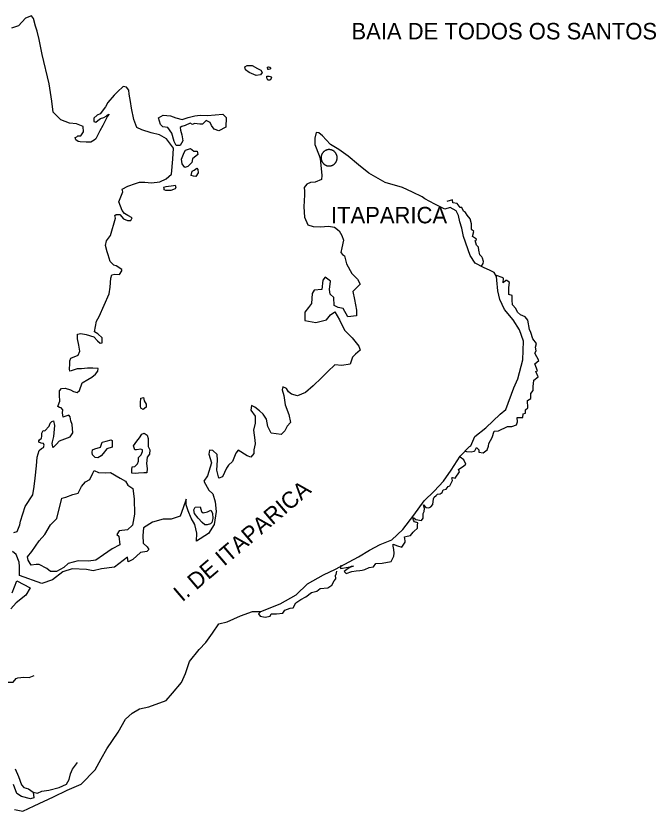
# Model space of a CAD drawing. Extents: x 662444 to 1640468, y 7452018 to 9606170.
# Drawn here: x 1173727 to 1199796, y 8540001 to 8572398 of the extents above; entities that cross this region are included whole.
import ezdxf

# ---------------------------------------------------------------- set-up
doc = ezdxf.new("R2010")
doc.units = 0
doc.layers.add('Level 1', color=7, linetype='Continuous')
doc.layers.add('Level 3', color=7, linetype='Continuous')

msp = doc.modelspace()

# ---------------------------------------------------------------- linework, layer by layer
at = {"layer": 'Level 1'}
for points in [[(1178235, 8569500), (1178093, 8569515), (1177870, 8569309), (1177725, 8569168), (1177466, 8568874), (1177375, 8568698), (1177160, 8568403), (1177039, 8568350), (1176905, 8568231), (1176902, 8568098), (1176977, 8568062), (1177066, 8568138), (1177177, 8568213), (1177309, 8568255), (1177398, 8568319), (1177454, 8568373), (1177520, 8568394), (1177453, 8568318), (1177269, 8567933), (1177143, 8567713), (1177029, 8567494), (1176983, 8567384), (1176916, 8567330), (1176783, 8567255), (1176586, 8567249), (1176347, 8567266), (1176260, 8567279), (1176163, 8567348), (1176144, 8567437), (1176210, 8567469), (1176244, 8567513), (1176374, 8567510), (1176477, 8567674), (1176460, 8567897), (1176190, 8568004), (1175907, 8568033), (1175561, 8568164), (1175241, 8568472), (1175187, 8568929), (1175084, 8569632), (1174796, 8570830), (1174669, 8571433), (1174589, 8571769), (1174518, 8571982), (1174449, 8572295), (1174365, 8572398), (1174111, 8572303), (1173831, 8571999), (1173545, 8571894)], [(1183227, 8570090), (1183077, 8570194), (1183047, 8570328), (1183147, 8570382), (1183354, 8570376), (1183570, 8570260), (1183699, 8570190), (1183751, 8570089), (1183683, 8569990), (1183508, 8569972), (1183227, 8570090)], [(1184071, 8570225), (1184016, 8570216), (1183983, 8570216), (1183975, 8570306), (1184008, 8570316), (1184073, 8570314), (1184105, 8570280), (1184071, 8570225)], [(1184082, 8569780), (1183984, 8569782), (1183952, 8569839), (1183943, 8569906), (1183944, 8569939), (1184042, 8569937), (1184096, 8569935), (1184138, 8569868), (1184082, 8569780)], [(1175879, 8556130), (1175724, 8556078), (1175647, 8556047), (1175619, 8556225), (1175633, 8556347), (1175569, 8556427), (1175504, 8556440), (1175440, 8556486), (1175487, 8556640), (1175510, 8556695), (1175495, 8556940), (1175499, 8557129), (1175578, 8557217), (1175731, 8557235), (1175947, 8557163), (1176077, 8557093), (1176218, 8557056), (1176318, 8557143), (1176424, 8557452), (1176656, 8557580), (1176822, 8557676), (1176967, 8557806), (1177057, 8557926), (1177082, 8558036), (1176853, 8558042), (1176646, 8558047), (1176394, 8558020), (1176219, 8558013), (1175977, 8557941), (1175922, 8557920), (1175903, 8558010), (1175919, 8558221), (1175922, 8558343), (1175957, 8558453), (1176266, 8558579), (1176335, 8558733), (1176286, 8558979), (1176238, 8559247), (1176232, 8559425), (1176375, 8559455), (1176592, 8559417), (1176895, 8559320), (1177044, 8559161), (1177161, 8559058), (1177238, 8559078), (1177243, 8559278), (1177061, 8559439), (1176933, 8559531), (1177009, 8559963), (1177123, 8560149), (1177527, 8561074), (1177567, 8561351), (1177597, 8561706), (1177633, 8561850), (1177754, 8561880), (1177939, 8561865), (1178041, 8562007), (1178042, 8562062), (1177806, 8562213), (1177709, 8562248), (1177559, 8562386), (1177490, 8562665), (1177449, 8562789), (1177379, 8563046), (1177416, 8563235), (1177585, 8563453), (1177777, 8564160), (1177758, 8564272), (1177813, 8564304), (1177955, 8564301), (1178104, 8564130), (1178266, 8564059), (1178408, 8564056), (1178465, 8564177), (1178282, 8564270), (1178153, 8564351), (1178057, 8564465), (1177913, 8564824), (1178087, 8565232), (1178057, 8565333), (1178278, 8565461), (1178597, 8565564), (1178762, 8565627), (1178981, 8565622), (1179253, 8565593), (1179581, 8565640), (1179846, 8565756), (1180058, 8565951), (1180117, 8566562), (1180139, 8567006), (1179853, 8567391), (1179574, 8567554), (1179237, 8567629), (1178858, 8567761), (1178653, 8567855), (1178530, 8568180), (1178432, 8568639), (1178395, 8568907), (1178337, 8569209), (1178319, 8569376), (1178235, 8569500)], [(1180495, 8568177), (1180737, 8568260), (1181012, 8568331), (1181230, 8568348), (1181525, 8568341), (1181842, 8568366), (1182148, 8568392), (1182287, 8568255), (1182277, 8567866), (1181990, 8567717), (1181795, 8567778), (1181690, 8567936), (1181638, 8568049), (1181476, 8568131), (1181320, 8567990), (1181222, 8567992), (1180993, 8568009), (1180916, 8567977), (1180829, 8568024), (1180620, 8567929), (1180488, 8567888), (1180421, 8567845), (1180430, 8567745), (1180480, 8567554), (1180528, 8567308), (1180414, 8567122), (1180250, 8567115), (1180167, 8567284), (1180077, 8567620), (1179919, 8567846), (1179713, 8567884), (1179617, 8567976), (1179536, 8568245), (1179724, 8568351), (1180018, 8568333), (1180234, 8568239), (1180495, 8568177)], [(1176381, 8541099), (1176951, 8541686), (1177192, 8542136), (1177431, 8542542), (1177895, 8543220), (1178191, 8543747), (1178459, 8543985), (1178758, 8544166), (1179141, 8544246), (1179846, 8544507), (1180104, 8544812), (1180464, 8545237), (1180626, 8545611), (1180791, 8546096), (1181195, 8546587), (1181464, 8546870), (1181736, 8547252), (1181985, 8547635), (1182336, 8547705), (1182877, 8547958), (1183361, 8548135), (1183699, 8548127), (1184492, 8548441), (1185145, 8548814), (1185603, 8549259), (1186246, 8549632), (1186742, 8549853), (1187682, 8550364), (1188125, 8550631), (1188557, 8550865), (1189041, 8551053), (1189477, 8551476), (1189928, 8552055), (1190358, 8552645), (1190760, 8553035), (1191142, 8553449), (1191447, 8553886), (1191822, 8554455), (1192203, 8554857), (1192247, 8554879), (1192420, 8555264), (1192866, 8555609), (1193447, 8556173), (1193681, 8556367), (1194009, 8557249), (1194160, 8557612), (1194376, 8558386), (1194395, 8559142), (1194232, 8559614), (1193970, 8560021), (1193620, 8560430), (1193434, 8560847), (1193355, 8561194), (1193311, 8561629), (1193293, 8561774), (1193199, 8561943), (1193037, 8562025), (1192767, 8562143), (1192433, 8562318), (1192223, 8562635), (1191959, 8563410), (1191880, 8563745), (1191799, 8564003), (1191751, 8564272), (1191657, 8564452), (1191409, 8564592), (1191190, 8564530), (1190780, 8564730), (1190381, 8564940), (1190274, 8565032), (1189875, 8565220), (1189465, 8565408), (1188760, 8565615), (1188093, 8565987), (1187676, 8566331), (1187259, 8566687), (1186872, 8566952), (1186539, 8567160), (1186358, 8567354), (1186209, 8567514), (1186060, 8567640), (1185951, 8567653), (1185901, 8567421), (1185895, 8567154), (1186080, 8566716), (1186110, 8566593), (1186180, 8565890), (1186176, 8565734), (1185911, 8565618), (1185726, 8565612), (1185571, 8565538), (1185470, 8565407), (1185477, 8565251), (1185473, 8565106), (1185450, 8564617), (1185483, 8564194), (1185618, 8563890), (1185834, 8563818), (1186129, 8563810), (1186457, 8563836), (1186696, 8563785)], [(1180582, 8566829), (1180628, 8566928), (1180837, 8566989), (1180976, 8566886), (1181107, 8566882), (1181137, 8566748), (1180914, 8566576), (1180888, 8566420), (1180721, 8566258), (1180600, 8566227), (1180494, 8566375), (1180466, 8566564), (1180582, 8566829)], [(1186809, 8566609), (1186809, 8566620), (1186809, 8566632), (1186808, 8566643), (1186807, 8566655), (1186805, 8566667), (1186803, 8566678), (1186801, 8566690), (1186798, 8566701), (1186795, 8566712), (1186792, 8566724), (1186788, 8566734), (1186784, 8566745), (1186780, 8566756), (1186775, 8566766), (1186770, 8566777), (1186763, 8566787), (1186758, 8566797), (1186752, 8566806), (1186744, 8566816), (1186738, 8566825), (1186731, 8566834), (1186723, 8566842), (1186715, 8566851), (1186707, 8566859), (1186699, 8566867), (1186690, 8566874), (1186681, 8566882), (1186672, 8566889), (1186662, 8566895), (1186653, 8566902), (1186643, 8566908), (1186633, 8566913), (1186623, 8566918), (1186612, 8566923), (1186602, 8566928), (1186591, 8566931), (1186580, 8566935), (1186570, 8566938), (1186558, 8566941), (1186547, 8566943), (1186536, 8566946), (1186524, 8566947), (1186513, 8566949), (1186501, 8566950), (1186490, 8566950), (1186479, 8566951), (1186467, 8566950), (1186456, 8566949), (1186444, 8566948), (1186433, 8566946), (1186422, 8566944), (1186410, 8566942), (1186399, 8566939), (1186388, 8566936), (1186377, 8566933), (1186367, 8566929), (1186356, 8566925), (1186345, 8566920), (1186335, 8566915), (1186325, 8566910), (1186315, 8566903), (1186305, 8566898), (1186297, 8566892), (1186287, 8566884), (1186278, 8566878), (1186269, 8566870), (1186261, 8566862), (1186252, 8566854), (1186244, 8566846), (1186236, 8566838), (1186230, 8566829), (1186222, 8566819), (1186215, 8566810), (1186209, 8566800), (1186202, 8566791), (1186197, 8566781), (1186191, 8566771), (1186186, 8566760), (1186182, 8566749), (1186177, 8566739), (1186174, 8566728), (1186170, 8566717), (1186166, 8566706), (1186164, 8566694), (1186161, 8566682), (1186159, 8566671), (1186158, 8566659), (1186156, 8566648), (1186155, 8566636), (1186155, 8566625), (1186154, 8566614), (1186155, 8566601), (1186156, 8566590), (1186157, 8566578), (1186159, 8566567), (1186161, 8566556), (1186162, 8566543), (1186165, 8566532), (1186168, 8566521), (1186171, 8566510)], [(1186171, 8566510), (1186176, 8566500), (1186180, 8566488), (1186184, 8566477), (1186189, 8566467), (1186194, 8566457), (1186200, 8566447), (1186206, 8566437), (1186212, 8566428), (1186219, 8566417), (1186226, 8566408), (1186233, 8566399), (1186241, 8566391), (1186249, 8566382), (1186256, 8566374), (1186265, 8566366), (1186274, 8566359), (1186283, 8566351), (1186292, 8566344), (1186301, 8566339), (1186311, 8566332), (1186321, 8566326), (1186330, 8566320), (1186341, 8566315), (1186352, 8566311), (1186362, 8566306), (1186373, 8566302), (1186383, 8566299), (1186394, 8566295), (1186406, 8566293), (1186417, 8566290), (1186428, 8566288), (1186440, 8566286), (1186451, 8566285), (1186463, 8566283), (1186474, 8566283), (1186485, 8566283), (1186497, 8566284), (1186508, 8566284), (1186520, 8566285), (1186531, 8566287), (1186541, 8566289), (1186554, 8566291), (1186565, 8566294), (1186576, 8566297), (1186587, 8566300), (1186596, 8566305), (1186607, 8566309), (1186618, 8566313), (1186628, 8566318), (1186638, 8566324), (1186648, 8566330), (1186658, 8566335), (1186667, 8566342), (1186677, 8566349), (1186686, 8566356), (1186695, 8566363), (1186703, 8566371), (1186712, 8566380), (1186720, 8566387), (1186728, 8566396), (1186734, 8566405), (1186742, 8566414), (1186749, 8566423), (1186755, 8566433), (1186761, 8566443), (1186767, 8566453), (1186773, 8566463), (1186777, 8566474), (1186782, 8566485), (1186787, 8566495), (1186790, 8566506), (1186794, 8566517), (1186797, 8566528), (1186800, 8566540), (1186802, 8566551), (1186805, 8566562), (1186806, 8566574), (1186808, 8566585), (1186809, 8566597), (1186809, 8566609)], [(1181049, 8565860), (1180962, 8565862), (1180865, 8565898), (1180902, 8566075), (1180990, 8566106), (1181101, 8566193), (1181132, 8566136), (1181151, 8566002), (1181049, 8565860)], [(1180145, 8565493), (1180211, 8565503), (1180242, 8565413), (1180218, 8565347), (1180031, 8565284), (1179834, 8565278), (1179770, 8565313), (1179760, 8565369), (1179751, 8565425), (1179849, 8565445), (1180145, 8565493)], [(1192692, 8562201), (1192761, 8562310), (1192774, 8562388), (1192722, 8562523), (1192702, 8562579), (1192617, 8562670), (1192578, 8562849), (1192559, 8562972), (1192485, 8563063), (1192435, 8563253), (1192456, 8563230), (1192480, 8563297), (1192319, 8563412), (1192378, 8563611), (1192282, 8563691), (1192284, 8563769), (1192277, 8563925), (1192227, 8564126), (1192100, 8564274), (1192037, 8564387), (1191952, 8564445), (1191890, 8564591), (1191824, 8564593), (1191697, 8564752), (1191523, 8564778), (1191504, 8564901), (1191274, 8564840)], [(1186696, 8563785), (1186889, 8563647), (1187004, 8563455), (1187065, 8563264), (1187002, 8562943), (1186965, 8562755), (1187028, 8562675), (1187114, 8562618), (1187194, 8562293), (1187413, 8561909), (1187637, 8561670), (1187741, 8561467), (1187449, 8561163), (1187518, 8560850), (1187594, 8560403), (1187600, 8560180), (1187238, 8560144), (1187050, 8560483), (1186855, 8560521), (1186682, 8560603), (1186679, 8560926), (1186530, 8561063), (1186502, 8561253), (1186532, 8561597), (1186318, 8561747), (1186228, 8561638), (1186185, 8561250), (1185868, 8561224), (1185789, 8561093), (1185757, 8560682), (1185643, 8560518), (1185486, 8560333), (1185499, 8559987), (1185934, 8559910), (1186373, 8560010), (1186531, 8560218), (1186708, 8560336), (1186908, 8560019), (1187105, 8559591), (1187414, 8559283), (1187689, 8558943), (1187739, 8558786), (1187561, 8558612), (1187427, 8558493), (1187332, 8558206), (1186993, 8558159), (1186709, 8558177), (1186430, 8557917), (1186173, 8557656), (1185826, 8557331), (1185525, 8557060), (1185194, 8556913), (1184956, 8556986), (1184827, 8557078), (1184743, 8557224), (1184592, 8557284), (1184567, 8557162), (1184638, 8556927), (1184694, 8556547), (1184837, 8556154), (1184905, 8555830), (1184771, 8555688), (1184678, 8555490), (1184533, 8555349), (1184120, 8555393), (1183984, 8555663), (1183926, 8555965), (1183790, 8556169), (1183651, 8556306), (1183459, 8556455), (1183318, 8556525), (1183292, 8556337), (1183471, 8556088), (1183475, 8555809), (1183403, 8555522), (1183458, 8555109), (1183476, 8554964), (1183416, 8554721), (1183412, 8554576), (1183288, 8554423), (1183147, 8554471), (1182771, 8554703), (1182681, 8554583), (1182542, 8554242), (1182385, 8554101), (1182306, 8553969), (1182133, 8553617), (1181990, 8553565), (1181911, 8553890), (1181932, 8554301), (1181927, 8554524), (1181746, 8554695), (1181604, 8554710), (1181589, 8554543), (1181689, 8554185), (1181523, 8553655), (1181376, 8553436), (1181585, 8553075), (1181745, 8552926), (1181846, 8552601), (1181880, 8552200)], [(1191991, 8554674), (1192078, 8554649), (1192263, 8554644), (1192384, 8554664), (1192417, 8554685), (1192486, 8554817), (1192581, 8554714), (1192580, 8554681), (1192579, 8554625), (1192753, 8554599), (1192920, 8554717), (1192978, 8554871), (1192981, 8554982), (1193118, 8555224), (1193201, 8555478), (1193376, 8555496), (1193740, 8555664), (1193926, 8555671), (1194113, 8555733), (1194149, 8555866), (1194142, 8556033), (1194284, 8556040), (1194372, 8556038), (1194386, 8556182), (1194474, 8556214), (1194478, 8556347), (1194578, 8556434), (1194563, 8556723), (1194697, 8556809), (1194691, 8557020), (1194792, 8557140), (1194786, 8557319), (1194799, 8557407), (1194824, 8557551), (1194992, 8557692), (1194899, 8557906), (1194965, 8557937), (1194852, 8558218), (1195019, 8558359), (1194852, 8558652), (1194909, 8558751), (1194891, 8558896), (1194928, 8559051), (1194780, 8559244), (1194699, 8559502), (1194636, 8559626), (1194569, 8559995), (1194463, 8560131), (1194269, 8560225), (1194152, 8560328), (1194079, 8560474), (1193952, 8560633), (1193935, 8560823), (1193940, 8561012), (1193799, 8561049), (1193803, 8561205), (1193806, 8561327), (1193833, 8561538), (1193715, 8561619), (1193682, 8561620), (1193571, 8561522), (1193586, 8561711), (1193522, 8561746), (1193294, 8561818)], [(1179032, 8556576), (1179029, 8556464), (1178906, 8556356), (1178809, 8556414), (1178801, 8556503), (1178804, 8556637), (1178809, 8556826), (1178918, 8556845), (1178948, 8556722), (1179032, 8556576)], [(1173645, 8551346), (1173777, 8551387), (1173893, 8551662), (1173918, 8551817), (1174107, 8552413), (1174414, 8552884), (1174466, 8553228), (1174517, 8553560), (1174563, 8554071), (1174593, 8554415), (1174676, 8554691), (1174765, 8554767), (1174854, 8554820), (1174878, 8554909), (1174847, 8554976), (1174760, 8554989), (1174663, 8555036), (1174664, 8555092), (1174687, 8555125), (1174765, 8555190), (1174778, 8555278), (1174781, 8555401), (1174838, 8555510), (1174903, 8555498), (1175082, 8555682), (1175118, 8555804), (1175196, 8555880), (1175251, 8555901), (1175301, 8555710), (1175257, 8555266), (1175197, 8555045), (1175185, 8554979), (1175214, 8554845), (1175246, 8554811), (1175369, 8554941), (1175504, 8555082), (1175724, 8555166), (1175933, 8555250), (1176046, 8555414), (1176011, 8555749), (1175960, 8555894), (1175931, 8556062), (1175879, 8556130)], [(1178758, 8555214), (1178860, 8555356), (1178948, 8555398), (1179066, 8555318), (1179106, 8555183), (1179114, 8555038), (1179109, 8554849), (1179182, 8554714), (1179167, 8554536), (1179077, 8554416), (1179049, 8554161), (1179065, 8553960), (1179061, 8553782), (1178941, 8553785), (1178722, 8553768), (1178591, 8553761), (1178450, 8553764), (1178453, 8553909), (1178456, 8554020), (1178565, 8554039), (1178677, 8554148), (1178713, 8554258), (1178716, 8554403), (1178828, 8554511), (1178886, 8554654), (1178888, 8554721), (1178812, 8554745), (1178637, 8554716), (1178571, 8554718), (1178521, 8554886), (1178645, 8555072), (1178758, 8555214)], [(1177167, 8554830), (1177237, 8555029), (1177402, 8555069), (1177599, 8555120), (1177653, 8555096), (1177647, 8554830), (1177427, 8554757), (1177280, 8554572), (1177202, 8554473), (1177058, 8554388), (1176949, 8554413), (1176843, 8554516), (1176834, 8554616), (1176848, 8554716), (1176947, 8554758), (1177167, 8554830)], [(1186954, 8550026), (1186950, 8549881), (1187257, 8549941), (1187476, 8549980), (1187388, 8549960), (1187256, 8549885), (1187100, 8549766), (1187174, 8549676), (1187405, 8549759), (1187580, 8549788), (1187734, 8549806), (1187821, 8549815), (1187931, 8549846), (1188108, 8549930), (1188283, 8549959), (1188384, 8550090), (1188636, 8550106), (1189008, 8550175), (1189112, 8550384), (1189126, 8550506), (1189119, 8550662), (1189089, 8550796), (1189091, 8550874), (1189264, 8550803), (1189437, 8550754), (1189573, 8550951), (1189575, 8551006), (1189557, 8551174), (1189656, 8551205), (1189798, 8551223), (1189900, 8551365), (1189933, 8551387), (1190079, 8551528), (1190082, 8551650), (1190095, 8551750), (1189954, 8551787), (1189923, 8551854), (1189893, 8551944), (1189926, 8551943), (1190011, 8551886), (1190239, 8551835), (1190307, 8551934), (1190309, 8552001), (1190312, 8552123), (1190358, 8552200), (1190361, 8552333), (1190321, 8552479), (1190416, 8552365), (1190547, 8552362), (1190624, 8552393), (1190703, 8552491), (1190731, 8552724), (1190754, 8552791), (1190843, 8552855), (1190899, 8552909), (1191009, 8552929), (1191086, 8552983), (1191122, 8553093), (1191243, 8553123), (1191332, 8553221), (1191399, 8553253), (1191502, 8553473), (1191473, 8553585), (1191506, 8553595), (1191614, 8553559), (1191784, 8553822), (1191754, 8553923), (1191965, 8554062), (1192043, 8554138), (1191971, 8554307), (1191821, 8554422)], [(1175393, 8551915), (1175599, 8552744), (1175764, 8552796), (1176050, 8552900), (1176259, 8552950), (1176396, 8553225), (1176565, 8553410), (1176731, 8553517), (1176857, 8553770), (1176914, 8553880), (1177087, 8553798), (1177359, 8553780), (1177578, 8553797), (1177976, 8553564), (1178191, 8553437), (1178285, 8553279), (1178489, 8553140), (1178544, 8552727), (1178561, 8552093), (1178474, 8551650), (1178273, 8551466), (1177934, 8551418), (1177843, 8551265), (1177917, 8551196), (1177952, 8550850), (1177643, 8550680), (1177299, 8550444), (1176988, 8550229), (1176681, 8550181), (1176256, 8550191), (1175861, 8550090), (1175672, 8549928), (1175384, 8549768), (1175133, 8549763), (1174983, 8549878), (1174671, 8550052), (1174551, 8550044), (1174354, 8550027), (1174228, 8550219), (1174199, 8550364), (1174379, 8550571), (1174673, 8551009), (1174898, 8551270), (1175136, 8551665), (1175393, 8551915)], [(1181880, 8552200), (1181802, 8551679), (1181574, 8551306), (1181087, 8550995), (1181095, 8551329), (1181016, 8551676), (1180870, 8551935), (1180735, 8552228), (1180654, 8552475), (1180660, 8552708), (1180531, 8552355), (1180414, 8552013), (1180051, 8551900), (1179724, 8551897), (1179295, 8551774), (1178929, 8551538), (1178889, 8551228), (1178914, 8550916), (1179074, 8550767), (1179137, 8550665), (1179058, 8550578), (1178806, 8550540), (1178494, 8550247), (1178295, 8550152), (1178267, 8550342), (1177745, 8549943), (1177208, 8549868), (1176879, 8549787), (1176597, 8549849), (1176019, 8549875), (1175635, 8549751), (1175212, 8549416), (1174783, 8549271), (1173875, 8549594), (1173873, 8549961), (1173855, 8550139), (1173743, 8550453), (1173583, 8550580)], [(1181005, 8552121), (1180977, 8552278), (1181023, 8552377), (1181230, 8552394), (1181291, 8552203), (1181355, 8552146), (1181531, 8552197), (1181663, 8552261), (1181726, 8552137), (1181742, 8551925), (1181706, 8551759), (1181650, 8551705), (1181518, 8551663), (1181420, 8551666), (1181313, 8551758), (1181154, 8551939), (1181005, 8552121)], [(1183699, 8548127), (1183599, 8548040), (1183672, 8547938), (1183879, 8547900), (1184087, 8547939), (1184122, 8548038), (1184340, 8548033), (1184592, 8548071), (1184682, 8548191), (1184892, 8548275), (1185023, 8548283), (1185126, 8548492), (1185326, 8548620), (1185536, 8548726), (1185758, 8548910), (1185978, 8548960), (1186111, 8549068), (1186428, 8549093), (1186595, 8549201), (1186687, 8549387), (1186754, 8549464), (1186747, 8549608), (1186769, 8549641), (1186795, 8549774)], [(1173574, 8548889), (1173771, 8549385), (1174310, 8549093), (1174128, 8548797), (1173738, 8548484), (1173525, 8548245)], [(1173277, 8545247), (1173615, 8545250), (1173739, 8545403), (1173805, 8545424), (1174046, 8545451), (1174264, 8545446), (1174473, 8545530)], [(1173703, 8541722), (1173837, 8541407), (1173948, 8541070), (1174044, 8540968), (1174239, 8540907), (1174432, 8540769), (1174459, 8540535), (1174316, 8540494), (1173958, 8540592), (1173765, 8540719), (1173632, 8541078)], [(1174432, 8540769), (1174605, 8540732), (1174782, 8540816), (1175066, 8540854), (1175483, 8540966), (1175792, 8541092), (1175895, 8541289), (1175944, 8541522), (1176025, 8541709), (1176239, 8541982)], [(1173673, 8540065), (1174009, 8540001), (1174472, 8540212), (1175256, 8540582), (1175819, 8540857), (1176381, 8541099)]]:
    msp.add_lwpolyline(points, dxfattribs=at)

# ---------------------------------------------------------------- texts
at = {"layer": 'Level 3'}
for s, height, p in [('BAIA DE TODOS OS SANTOS', 670.01, (1187391, 8571441)), ('ITAPARICA', 669.8, (1186558, 8563947))]:
    msp.add_text(s, height=height, dxfattribs=at).set_placement(p)
msp.add_text('I. DE ITAPARICA', height=669.39, rotation=40.451, dxfattribs=at).set_placement((1180501, 8548499))

doc.saveas('drawing.dxf')
